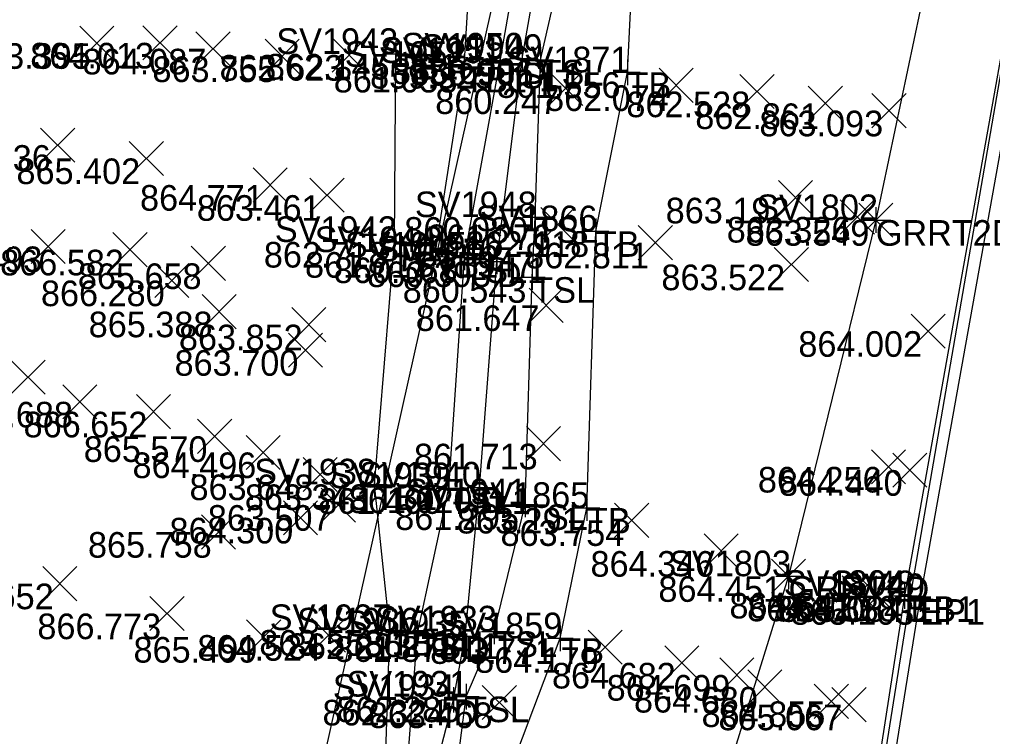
# Model space of a CAD drawing. Extents: x 2228183 to 2230895, y 679226 to 682223.
# Drawn here: x 2228233.78 to 2228271.79, y 680414.86 to 680442.86 of the extents above; entities that cross this region are included whole.
import ezdxf

# ---------------------------------------------------------------- set-up
doc = ezdxf.new("R2010")
doc.units = 0
for name, color, linetype in [('DR_X_Ditch', 7, 'Continuous'), ('PV_X_EOP', 7, 'Continuous'), ('PV_X_Shoulder_Aggregate', 7, 'Continuous'), ('RD_X_GR_Rt', 7, 'Continuous'), ('SC_Scratch1', 7, 'Continuous'), ('SV_P_Control_Cells_Set', 7, 'Continuous'), ('SV_X_Break_Lines', 7, 'Continuous'), ('SV_X_Random_Point', 7, 'Continuous'), ('SV_X_Shot_Marker', 7, 'Continuous'), ('SV_X_Text_Comment', 7, 'Continuous'), ('SV_X_Toe_of_Slope', 7, 'Continuous'), ('SV_X_Top_of_Bank', 7, 'Continuous'), ('VG_X_Tree_Line_Rt', 7, 'Continuous')]:
    doc.layers.add(name, color=color, linetype=linetype)

msp = doc.modelspace()

# ---------------------------------------------------------------- linework, layer by layer
at = {"layer": 'DR_X_Ditch'}
msp.add_lwpolyline([(2228248.152, 680398.096), (2228249.095, 680405.268), (2228249.691, 680412.267), (2228250.738, 680416.294), (2228251.182, 680418.776), (2228251.754, 680424.586), (2228252.425, 680433.411), (2228253.413, 680441.336), (2228254.696, 680448.568), (2228253.869, 680453.653), (2228253.021, 680456.333), (2228253.924, 680458.912), (2228254.395, 680462.481), (2228255.204, 680465.484), (2228255.304, 680468.353), (2228255.892, 680471.795), (2228254.699, 680480.343), (2228253.82, 680482.578)], dxfattribs=at)
at = {"layer": 'PV_X_EOP'}
msp.add_lwpolyline([(2228252.395, 680193.158), (2228252.017, 680217.928), (2228252.166, 680243.969), (2228252.969, 680269.118), (2228254.41, 680295.326), (2228256.289, 680320.959), (2228258.609, 680345.957), (2228261.353, 680370.084), (2228265.081, 680396.038), (2228268.964, 680420.227), (2228273.571, 680445.935), (2228278.026, 680470.103), (2228282.912, 680494.405), (2228287.764, 680519.213), (2228292.491, 680542.983), (2228297.123, 680567.244), (2228301.725, 680591.365), (2228306.593, 680616.395), (2228311.35, 680641.501), (2228316.271, 680666.166), (2228321.17, 680690.642)], dxfattribs=at)
at = {"layer": 'PV_X_Shoulder_Aggregate'}
msp.add_lwpolyline([(2228251.688, 680193.163), (2228251.4, 680217.895), (2228251.524, 680243.996), (2228252.468, 680269.192), (2228253.879, 680295.388), (2228256.006, 680320.988), (2228258.289, 680346.01), (2228261.054, 680370.168), (2228264.719, 680396.078), (2228268.579, 680420.338), (2228273.034, 680446.093), (2228277.679, 680470.182), (2228282.388, 680494.533), (2228287.18, 680519.364), (2228291.91, 680543.114), (2228296.422, 680567.366), (2228298.906, 680579.954), (2228299.502, 680580.4), (2228300.213, 680585.238), (2228301.248, 680591.351), (2228306.286, 680616.474), (2228310.79, 680641.597), (2228315.628, 680666.277), (2228320.418, 680690.758)], dxfattribs=at)
at = {"layer": 'RD_X_GR_Rt'}
msp.add_lwpolyline([(2228317.277, 680691.491), (2228312.595, 680666.948), (2228307.846, 680642.212), (2228302.988, 680616.983), (2228299.878, 680601.719), (2228297.761, 680591.905), (2228295.954, 680582.306), (2228293.417, 680567.926), (2228288.785, 680543.533), (2228284.091, 680519.921), (2228279.274, 680495.191), (2228277.122, 680484.488), (2228274.573, 680472.619), (2228272.345, 680459.942), (2228269.701, 680446.744), (2228267.226, 680435.025), (2228263.818, 680421.121), (2228260.268, 680409.699)], dxfattribs=at)
at = {"layer": 'SV_X_Break_Lines'}
msp.add_lwpolyline([(2228320.273, 680690.8), (2228315.504, 680666.348), (2228310.738, 680641.634), (2228307.941, 680626.405), (2228307.393, 680623.472), (2228306.032, 680616.453), (2228303.053, 680601.155), (2228302.136, 680596.655), (2228301.06, 680591.437), (2228300.056, 680585.377), (2228299.678, 680583.167), (2228299.406, 680580.537), (2228298.77, 680580.019), (2228296.305, 680567.394), (2228291.772, 680543.248), (2228287.045, 680519.362), (2228285.465, 680511.012), (2228284.573, 680506.414), (2228282.283, 680494.649), (2228277.562, 680470.257), (2228272.956, 680446.158), (2228268.352, 680420.353), (2228266.832, 680410.603), (2228265.647, 680402.172)], dxfattribs=at)
at = {"layer": 'SV_X_Random_Point'}
for p, q in [((2228236.133, 680441.265), (2228237.467, 680442.6)), ((2228236.133, 680442.6), (2228237.467, 680441.265)), ((2228238.598, 680441.279), (2228239.932, 680442.614)), ((2228238.598, 680442.614), (2228239.932, 680441.279)), ((2228240.673, 680441.047), (2228242.007, 680442.382)), ((2228240.673, 680442.382), (2228242.007, 680441.047)), ((2228245.992, 680440.804), (2228247.326, 680442.139)), ((2228245.992, 680442.139), (2228247.326, 680440.804)), ((2228243.376, 680440.749), (2228244.71, 680442.084)), ((2228243.376, 680442.084), (2228244.71, 680440.749)), ((2228254.448, 680439.5), (2228255.782, 680440.835)), ((2228254.448, 680440.835), (2228255.782, 680439.5)), ((2228258.764, 680439.619), (2228260.098, 680440.954)), ((2228258.764, 680440.954), (2228260.098, 680439.619)), ((2228261.918, 680439.377), (2228263.252, 680440.712)), ((2228261.918, 680440.712), (2228263.252, 680439.377)), ((2228264.592, 680438.914), (2228265.926, 680440.249)), ((2228264.592, 680440.249), (2228265.926, 680438.914)), ((2228267.078, 680438.631), (2228268.412, 680439.966)), ((2228267.078, 680439.966), (2228268.412, 680438.631)), ((2228234.605, 680437.285), (2228235.939, 680438.62)), ((2228234.605, 680438.62), (2228235.939, 680437.285)), ((2228238.067, 680436.765), (2228239.401, 680438.1)), ((2228238.067, 680438.1), (2228239.401, 680436.765)), ((2228242.902, 680435.727), (2228244.236, 680437.062)), ((2228242.902, 680437.062), (2228244.236, 680435.727)), ((2228245.121, 680435.332), (2228246.455, 680436.667)), ((2228245.121, 680436.667), (2228246.455, 680435.332)), ((2228263.426, 680435.231), (2228264.76, 680436.566)), ((2228263.426, 680436.566), (2228264.76, 680435.231)), ((2228265.841, 680434.482), (2228267.175, 680435.817)), ((2228265.841, 680435.817), (2228267.175, 680434.482)), ((2228266.559, 680434.358), (2228267.893, 680435.693)), ((2228266.559, 680435.693), (2228267.893, 680434.358)), ((2228254.141, 680434.187), (2228255.475, 680435.522)), ((2228254.141, 680435.522), (2228255.475, 680434.187)), ((2228234.234, 680433.328), (2228235.568, 680434.663)), ((2228234.234, 680434.663), (2228235.568, 680433.328)), ((2228237.43, 680433.201), (2228238.764, 680434.536)), ((2228237.43, 680434.536), (2228238.764, 680433.201)), ((2228257.947, 680433.474), (2228259.281, 680434.809)), ((2228257.947, 680434.809), (2228259.281, 680433.474)), ((2228240.491, 680432.668), (2228241.825, 680434.003)), ((2228240.491, 680434.003), (2228241.825, 680432.668)), ((2228263.259, 680432.622), (2228264.593, 680433.957)), ((2228263.259, 680433.957), (2228264.593, 680432.622)), ((2228239.064, 680431.998), (2228240.398, 680433.333)), ((2228239.064, 680433.333), (2228240.398, 680431.998)), ((2228253.687, 680431.029), (2228255.021, 680432.364)), ((2228253.687, 680432.364), (2228255.021, 680431.029)), ((2228240.915, 680430.785), (2228242.249, 680432.12)), ((2228240.915, 680432.12), (2228242.249, 680430.785)), ((2228244.412, 680430.275), (2228245.746, 680431.61)), ((2228244.412, 680431.61), (2228245.746, 680430.275)), ((2228268.608, 680430.021), (2228269.942, 680431.356)), ((2228268.608, 680431.356), (2228269.942, 680430.021)), ((2228244.284, 680429.281), (2228245.618, 680430.616)), ((2228244.284, 680430.616), (2228245.618, 680429.281)), ((2228233.443, 680428.225), (2228234.777, 680429.56)), ((2228233.443, 680429.56), (2228234.777, 680428.225)), ((2228235.467, 680427.262), (2228236.801, 680428.597)), ((2228235.467, 680428.597), (2228236.801, 680427.262)), ((2228238.346, 680426.876), (2228239.68, 680428.211)), ((2228238.346, 680428.211), (2228239.68, 680426.876)), ((2228240.735, 680425.916), (2228242.069, 680427.251)), ((2228240.735, 680427.251), (2228242.069, 680425.916)), ((2228253.584, 680425.627), (2228254.918, 680426.962)), ((2228253.584, 680426.962), (2228254.918, 680425.627)), ((2228242.632, 680425.286), (2228243.966, 680426.621)), ((2228242.632, 680426.621), (2228243.966, 680425.286)), ((2228244.854, 680424.425), (2228246.188, 680425.76)), ((2228244.854, 680425.76), (2228246.188, 680424.425)), ((2228267.058, 680424.722), (2228268.392, 680426.057)), ((2228267.058, 680426.057), (2228268.392, 680424.722)), ((2228267.891, 680424.595), (2228269.225, 680425.93)), ((2228267.891, 680425.93), (2228269.225, 680424.595)), ((2228245.564, 680423.23), (2228246.898, 680424.565)), ((2228245.564, 680424.565), (2228246.898, 680423.23)), ((2228244.086, 680422.733), (2228245.42, 680424.068)), ((2228244.086, 680424.068), (2228245.42, 680422.733)), ((2228257.024, 680422.638), (2228258.358, 680423.973)), ((2228257.024, 680423.973), (2228258.358, 680422.638)), ((2228240.887, 680422.179), (2228242.221, 680423.514)), ((2228240.887, 680423.514), (2228242.221, 680422.179)), ((2228260.521, 680421.436), (2228261.855, 680422.771)), ((2228260.521, 680422.771), (2228261.855, 680421.436)), ((2228263.151, 680420.454), (2228264.485, 680421.789)), ((2228263.151, 680421.789), (2228264.485, 680420.454)), ((2228234.688, 680420.166), (2228236.022, 680421.501)), ((2228234.688, 680421.501), (2228236.022, 680420.166)), ((2228265.916, 680419.806), (2228267.25, 680421.141)), ((2228265.916, 680421.141), (2228267.25, 680419.806)), ((2228266.648, 680419.696), (2228267.982, 680421.031)), ((2228266.648, 680421.031), (2228267.982, 680419.696)), ((2228238.874, 680418.996), (2228240.208, 680420.331)), ((2228238.874, 680420.331), (2228240.208, 680418.996)), ((2228242.651, 680418.081), (2228243.985, 680419.416)), ((2228242.651, 680419.416), (2228243.985, 680418.081)), ((2228245.184, 680418.154), (2228246.518, 680419.489)), ((2228245.184, 680419.489), (2228246.518, 680418.154)), ((2228255.991, 680417.683), (2228257.325, 680419.018)), ((2228255.991, 680419.018), (2228257.325, 680417.683)), ((2228258.985, 680417.07), (2228260.319, 680418.405)), ((2228258.985, 680418.405), (2228260.319, 680417.07)), ((2228261.131, 680416.598), (2228262.465, 680417.933)), ((2228261.131, 680417.933), (2228262.465, 680416.598)), ((2228262.229, 680416.131), (2228263.563, 680417.466)), ((2228262.229, 680417.466), (2228263.563, 680416.131)), ((2228251.857, 680415.525), (2228253.191, 680416.86)), ((2228251.857, 680416.86), (2228253.191, 680415.525)), ((2228264.825, 680415.566), (2228266.159, 680416.901)), ((2228264.825, 680416.901), (2228266.159, 680415.566)), ((2228265.512, 680415.441), (2228266.846, 680416.776)), ((2228265.512, 680416.776), (2228266.846, 680415.441))]:
    msp.add_line(p, q, dxfattribs=at)
at = {"layer": 'SV_X_Shot_Marker'}
for p, q in [((2228248.473, 680442.014), (2228248.473, 680441.014)), ((2228253.413, 680441.836), (2228253.413, 680440.836)), ((2228254.135, 680441.78), (2228254.135, 680440.78)), ((2228247.973, 680441.514), (2228248.973, 680441.514)), ((2228248.473, 680441.514), (2228248.473, 680441.514)), ((2228251.154, 680441.509), (2228251.154, 680440.509)), ((2228252.542, 680441.662), (2228252.542, 680440.662)), ((2228250.654, 680441.009), (2228251.654, 680441.009)), ((2228251.154, 680441.009), (2228251.154, 680441.009)), ((2228252.042, 680441.162), (2228253.042, 680441.162)), ((2228252.542, 680441.162), (2228252.542, 680441.162)), ((2228252.913, 680441.336), (2228253.913, 680441.336)), ((2228253.413, 680441.336), (2228253.413, 680441.336)), ((2228253.635, 680441.28), (2228254.635, 680441.28)), ((2228254.135, 680441.28), (2228254.135, 680441.28)), ((2228257.527, 680441.297), (2228257.527, 680440.297)), ((2228257.027, 680440.797), (2228258.027, 680440.797)), ((2228257.527, 680440.797), (2228257.527, 680440.797)), ((2228253.924, 680435.641), (2228253.924, 680434.641)), ((2228267.226, 680435.525), (2228267.226, 680434.525)), ((2228253.424, 680435.141), (2228254.424, 680435.141)), ((2228253.924, 680435.141), (2228253.924, 680435.141)), ((2228256.296, 680435.091), (2228256.296, 680434.091)), ((2228266.726, 680435.025), (2228267.726, 680435.025)), ((2228267.226, 680435.025), (2228267.226, 680435.025)), ((2228248.424, 680434.673), (2228248.424, 680433.673)), ((2228255.796, 680434.591), (2228256.796, 680434.591)), ((2228256.296, 680434.591), (2228256.296, 680434.591)), ((2228247.924, 680434.173), (2228248.924, 680434.173)), ((2228248.424, 680434.173), (2228248.424, 680434.173)), ((2228250.029, 680434.277), (2228250.029, 680433.277)), ((2228249.529, 680433.777), (2228250.529, 680433.777)), ((2228250.029, 680433.777), (2228250.029, 680433.777)), ((2228251.157, 680434.067), (2228251.157, 680433.067)), ((2228252.425, 680433.911), (2228252.425, 680432.911)), ((2228250.657, 680433.567), (2228251.657, 680433.567)), ((2228251.157, 680433.567), (2228251.157, 680433.567)), ((2228251.925, 680433.411), (2228252.925, 680433.411)), ((2228252.425, 680433.411), (2228252.425, 680433.411)), ((2228253.811, 680433.297), (2228253.811, 680432.297)), ((2228253.311, 680432.797), (2228254.311, 680432.797)), ((2228253.811, 680432.797), (2228253.811, 680432.797)), ((2228247.645, 680425.206), (2228247.645, 680424.206)), ((2228250.556, 680425.055), (2228250.556, 680424.055)), ((2228251.754, 680425.086), (2228251.754, 680424.086)), ((2228247.145, 680424.706), (2228248.145, 680424.706)), ((2228247.645, 680424.706), (2228247.645, 680424.706)), ((2228250.056, 680424.555), (2228251.056, 680424.555)), ((2228250.556, 680424.555), (2228250.556, 680424.555)), ((2228251.254, 680424.586), (2228252.254, 680424.586)), ((2228251.754, 680424.586), (2228251.754, 680424.586)), ((2228253.526, 680424.426), (2228253.526, 680423.426)), ((2228255.946, 680424.289), (2228255.946, 680423.289)), ((2228253.026, 680423.926), (2228254.026, 680423.926)), ((2228253.526, 680423.926), (2228253.526, 680423.926)), ((2228255.446, 680423.789), (2228256.446, 680423.789)), ((2228255.946, 680423.789), (2228255.946, 680423.789)), ((2228263.818, 680421.621), (2228263.818, 680420.621)), ((2228263.318, 680421.121), (2228264.318, 680421.121)), ((2228263.818, 680421.121), (2228263.818, 680421.121)), ((2228268.352, 680420.853), (2228268.352, 680419.853)), ((2228268.579, 680420.838), (2228268.579, 680419.838)), ((2228268.964, 680420.727), (2228268.964, 680419.727)), ((2228267.852, 680420.353), (2228268.852, 680420.353)), ((2228268.079, 680420.338), (2228269.079, 680420.338)), ((2228268.352, 680420.353), (2228268.352, 680420.353)), ((2228268.464, 680420.227), (2228269.464, 680420.227)), ((2228268.579, 680420.338), (2228268.579, 680420.338)), ((2228268.964, 680420.227), (2228268.964, 680420.227)), ((2228248.247, 680419.519), (2228248.247, 680418.519)), ((2228249.327, 680419.387), (2228249.327, 680418.387)), ((2228252.326, 680419.465), (2228252.326, 680418.465)), ((2228247.747, 680419.019), (2228248.747, 680419.019)), ((2228248.247, 680419.019), (2228248.247, 680419.019)), ((2228251.182, 680419.276), (2228251.182, 680418.276)), ((2228251.826, 680418.965), (2228252.826, 680418.965)), ((2228252.326, 680418.965), (2228252.326, 680418.965)), ((2228254.905, 680419.199), (2228254.905, 680418.199)), ((2228248.827, 680418.887), (2228249.827, 680418.887)), ((2228249.327, 680418.887), (2228249.327, 680418.887)), ((2228250.682, 680418.776), (2228251.682, 680418.776)), ((2228251.182, 680418.776), (2228251.182, 680418.776)), ((2228254.405, 680418.699), (2228255.405, 680418.699)), ((2228254.905, 680418.699), (2228254.905, 680418.699)), ((2228250.738, 680416.794), (2228250.738, 680415.794)), ((2228251.23, 680416.922), (2228251.23, 680415.922)), ((2228250.238, 680416.294), (2228251.238, 680416.294)), ((2228250.73, 680416.422), (2228251.73, 680416.422)), ((2228250.738, 680416.294), (2228250.738, 680416.294)), ((2228251.23, 680416.422), (2228251.23, 680416.422))]:
    msp.add_line(p, q, dxfattribs=at)
at = {"layer": 'SV_X_Toe_of_Slope'}
for points in [[(2228247.363, 680398.195), (2228248.549, 680405.269), (2228248.818, 680412.227), (2228249.327, 680418.887), (2228250.556, 680424.555), (2228251.157, 680433.567), (2228252.542, 680441.162), (2228253.839, 680448.589), (2228253.231, 680453.1), (2228252.107, 680454.105), (2228250.987, 680456.203), (2228252.313, 680459.504), (2228253.331, 680462.687), (2228254.374, 680464.819), (2228254.89, 680468.476), (2228255.601, 680471.521), (2228254.065, 680480.323), (2228253.345, 680482.191)], [(2228248.769, 680398.124), (2228249.858, 680405.177), (2228250.692, 680412.274), (2228251.23, 680416.422), (2228252.326, 680418.965), (2228253.526, 680423.926), (2228253.811, 680432.797), (2228253.924, 680435.141), (2228254.135, 680441.28), (2228255.741, 680448.336), (2228254.458, 680453.857), (2228254.543, 680454.732), (2228254.934, 680456.198), (2228255.832, 680458.437), (2228255.885, 680462.309), (2228256.037, 680464.674), (2228255.856, 680468.365), (2228256.292, 680472.05), (2228254.247, 680482.064)]]:
    msp.add_lwpolyline(points, dxfattribs=at)
at = {"layer": 'SV_X_Top_of_Bank'}
for points in [[(2228250.029, 680433.777), (2228251.154, 680441.009), (2228251.375, 680444.682), (2228252.914, 680448.735), (2228251.956, 680452.403), (2228251.067, 680453.803), (2228250.559, 680456.503), (2228251.93, 680459.772), (2228252.869, 680462.786), (2228253.86, 680464.754), (2228254.264, 680468.502), (2228255.305, 680471.493), (2228253.636, 680480.453), (2228253.345, 680482.191)], [(2228250.307, 680398.124), (2228251.813, 680405.02), (2228252.399, 680412.097), (2228254.905, 680418.699), (2228255.946, 680423.789), (2228256.296, 680434.591), (2228257.527, 680440.797), (2228257.898, 680448.164), (2228256.801, 680454.49), (2228258.019, 680458.203), (2228257.686, 680462.292), (2228256.963, 680468.691), (2228257.054, 680472.414), (2228255.862, 680480.443), (2228255.026, 680481.727), (2228254.275, 680482.126)], [(2228246.89, 680398.302), (2228247.542, 680405.142), (2228248.019, 680412.274), (2228248.247, 680419.019), (2228247.645, 680424.706), (2228248.424, 680434.173), (2228248.473, 680441.514)]]:
    msp.add_lwpolyline(points, dxfattribs=at)
at = {"layer": 'VG_X_Tree_Line_Rt'}
msp.add_lwpolyline([(2228242.224, 680398.608), (2228254.757, 680454.617), (2228285.377, 680608.953), (2228295.459, 680686.843), (2228290.96, 680699.609), (2228297.38, 680721.363), (2228313.146, 680792.869)], dxfattribs=at)

# ---------------------------------------------------------------- texts
at = {"layer": 'SC_Scratch1'}
for s, p in [('863.395', (2228231.73, 680440.932)), ('864.013', (2228234.201, 680440.946)), ('864.087', (2228236.244, 680440.714)), ('863.755', (2228238.973, 680440.416)), ('862.623', (2228241.595, 680440.471)), ('862.145', (2228243.403, 680440.514)), ('858.699', (2228248.329, 680440.336)), ('861.058', (2228246.054, 680440.009)), ('859.325', (2228247.472, 680440.162)), ('858.906', (2228249.031, 680440.28)), ('861.556', (2228252.423, 680439.797)), ('862.074', (2228254.309, 680439.286)), ('860.247', (2228250.019, 680439.167)), ('862.528', (2228257.485, 680439.044)), ('862.861', (2228260.177, 680438.581)), ('863.093', (2228262.681, 680438.298)), ('865.136', (2228230.168, 680436.952)), ('865.402', (2228233.661, 680436.432)), ('864.771', (2228238.487, 680435.394)), ('863.461', (2228240.706, 680434.999)), ('863.192', (2228259.02, 680434.898)), ('860.080', (2228248.81, 680434.141)), ('863.326', (2228261.404, 680434.149)), ('863.549', (2228262.142, 680434.025)), ('863.549', (2228262.142, 680434.025)), ('861.276', (2228249.704, 680433.854)), ('862.118', (2228251.196, 680433.591)), ('862.718', (2228243.324, 680433.173)), ('862.811', (2228253.532, 680433.141)), ('866.493', (2228229.837, 680432.995)), ('866.582', (2228233.024, 680432.868)), ('861.717', (2228244.933, 680432.777)), ('860.568', (2228246.057, 680432.567)), ('860.393', (2228247.361, 680432.411)), ('865.658', (2228236.058, 680432.335)), ('863.522', (2228258.853, 680432.289)), ('866.280', (2228234.617, 680431.665)), ('860.543', (2228248.747, 680431.797)), ('865.388', (2228236.482, 680430.452)), ('861.647', (2228249.258, 680430.696)), ('863.852', (2228240.006, 680429.942)), ('864.002', (2228264.202, 680429.688)), ('863.700', (2228239.837, 680428.948)), ('867.688', (2228231.034, 680426.929)), ('866.652', (2228233.94, 680426.543)), ('865.570', (2228236.288, 680425.583)), ('861.713', (2228249.187, 680425.294)), ('864.496', (2228238.195, 680424.953)), ('864.256', (2228262.621, 680424.389)), ('863.648', (2228240.421, 680424.092)), ('864.440', (2228263.444, 680424.262)), ('863.343', (2228242.581, 680423.706)), ('861.400', (2228245.442, 680423.555)), ('861.020', (2228246.64, 680423.586)), ('863.507', (2228241.135, 680422.897)), ('861.295', (2228248.456, 680422.926)), ('863.291', (2228250.864, 680422.789)), ('864.300', (2228239.639, 680422.4)), ('863.754', (2228252.569, 680422.305)), ('865.758', (2228236.454, 680421.846)), ('864.346', (2228256.084, 680421.103)), ('868.652', (2228230.282, 680419.833)), ('864.451', (2228258.736, 680420.121)), ('864.451', (2228258.736, 680420.121)), ('864.642', (2228261.51, 680419.473)), ('864.810', (2228262.201, 680419.363)), ('864.888', (2228263.252, 680419.353)), ('865.084', (2228263.457, 680419.338)), ('865.103', (2228263.9, 680419.227)), ('866.773', (2228234.477, 680418.663)), ('863.558', (2228243.147, 680418.019)), ('862.041', (2228247.244, 680417.965)), ('865.499', (2228238.234, 680417.748)), ('864.524', (2228240.729, 680417.821)), ('862.223', (2228244.263, 680417.887)), ('861.878', (2228246.082, 680417.776)), ('863.771', (2228249.823, 680417.699)), ('864.179', (2228251.574, 680417.35)), ('864.682', (2228254.579, 680416.737)), ('864.699', (2228256.714, 680416.265)), ('864.680', (2228257.782, 680415.798)), ('862.324', (2228245.616, 680415.294)), ('862.285', (2228246.16, 680415.422)), ('863.468', (2228247.424, 680415.192)), ('864.855', (2228260.422, 680415.233)), ('865.067', (2228261.083, 680415.108))]:
    msp.add_text(s, height=1, dxfattribs=at).set_placement(p)
at = {"layer": 'SV_P_Control_Cells_Set'}
for s, p in [('SV1943', (2228243.811, 680441.514)), ('SV1951', (2228247.862, 680441.162)), ('SV1950', (2228248.701, 680441.336)), ('SV1949', (2228249.453, 680441.28)), ('SV1952', (2228246.483, 680441.009)), ('SV1871', (2228252.847, 680440.797)), ('SV1948', (2228249.225, 680435.141)), ('SV1802', (2228262.555, 680435.025)), ('SV1866', (2228251.594, 680434.591)), ('SV1942', (2228243.753, 680434.173)), ('SV1944', (2228245.309, 680433.777)), ('SV1945', (2228246.488, 680433.567)), ('SV1946', (2228247.723, 680433.411)), ('SV1947', (2228249.117, 680432.797)), ('SV1938', (2228242.946, 680424.706)), ('SV1939', (2228245.874, 680424.555)), ('SV1940', (2228247.042, 680424.586)), ('SV1941', (2228248.846, 680423.926)), ('SV1865', (2228251.277, 680423.789)), ('SV1803', (2228259.156, 680421.121)), ('SV1804', (2228263.632, 680420.353)), ('SV48', (2228265.477, 680420.338)), ('SV49', (2228265.879, 680420.227)), ('SV1937', (2228243.553, 680419.019)), ('SV1936', (2228244.625, 680418.887)), ('SV1935', (2228246.513, 680418.776)), ('SV1933', (2228247.664, 680418.965)), ('SV1859', (2228250.223, 680418.699)), ('SV1931', (2228246.55, 680416.422)), ('SV1934', (2228246.018, 680416.294))]:
    msp.add_text(s, height=1, dxfattribs=at).set_placement(p)
at = {"layer": 'SV_X_Text_Comment'}
for s, p in [('TB1', (2228248.473, 680440.514)), ('TB1', (2228251.154, 680440.009)), ('TSL1', (2228252.542, 680440.162)), ('D', (2228253.413, 680440.336)), ('TSL', (2228254.135, 680440.28)), ('TB', (2228257.527, 680439.797)), ('TSL', (2228253.924, 680434.141)), ('GRRT2D', (2228267.226, 680434.025)), ('TB', (2228256.296, 680433.591)), ('TB1', (2228248.424, 680433.173)), ('TB1', (2228250.029, 680432.777)), ('TSL1', (2228251.157, 680432.567)), ('D', (2228252.425, 680432.411)), ('TSL', (2228253.811, 680431.797)), ('TB1', (2228247.645, 680423.706)), ('TSL1', (2228250.556, 680423.555)), ('D', (2228251.754, 680423.586)), ('TSL', (2228253.526, 680422.926)), ('TB', (2228255.946, 680422.789)), ('GRRT2D', (2228263.818, 680420.121)), ('B', (2228268.352, 680419.353)), ('EB1', (2228268.579, 680419.338)), ('EP1', (2228268.964, 680419.227)), ('TB1', (2228248.247, 680418.019)), ('TSL', (2228252.326, 680417.965)), ('TSL1', (2228249.327, 680417.887)), ('D', (2228251.182, 680417.776)), ('TB', (2228254.905, 680417.699)), ('D', (2228250.738, 680415.294)), ('TSL', (2228251.23, 680415.422))]:
    msp.add_text(s, height=1, dxfattribs=at).set_placement(p)

doc.saveas('drawing.dxf')
